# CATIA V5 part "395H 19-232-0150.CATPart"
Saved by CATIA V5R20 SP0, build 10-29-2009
Part number: 395H 19-232-0150
Source: Unknown
Bounding box of the stored display mesh (mm): x -36.355 to 36.355, y -36.355 to 36.355, z -125 to 20
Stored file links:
  C:\Users\Utente\Desktop\3D files 395H FCA\395H 19-232-0150.CATPart
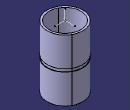
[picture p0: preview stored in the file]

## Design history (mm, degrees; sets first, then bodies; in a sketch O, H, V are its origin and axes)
Set1
  Line1 to Line3: stored without definition
  Point1 "Punto.4": stored without definition
Body1 (main body)
  Solid1 "PartBody": solid without history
